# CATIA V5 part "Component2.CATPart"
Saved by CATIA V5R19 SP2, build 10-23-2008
Part number: Component2
Definition: Component2
Nomenclature: Component2
Source: Unknown
Bounding box of the stored display mesh (mm): x -4.283 to 0.4, y 0 to 2.367, z 0 to 3.3
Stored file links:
  Z:\fausse table rondelle-20220905T211342Z-001\fausse table rondelle\Component2.CATPart
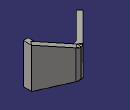
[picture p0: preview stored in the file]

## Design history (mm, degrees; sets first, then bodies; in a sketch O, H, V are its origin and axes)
AxisSystem1: origin (0, 0, 0), X (1, 0, 0), Y (0, 1, 0), Z (0, 0, 1)
Body1 "Body1" (main body)
  Solid1: solid without history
